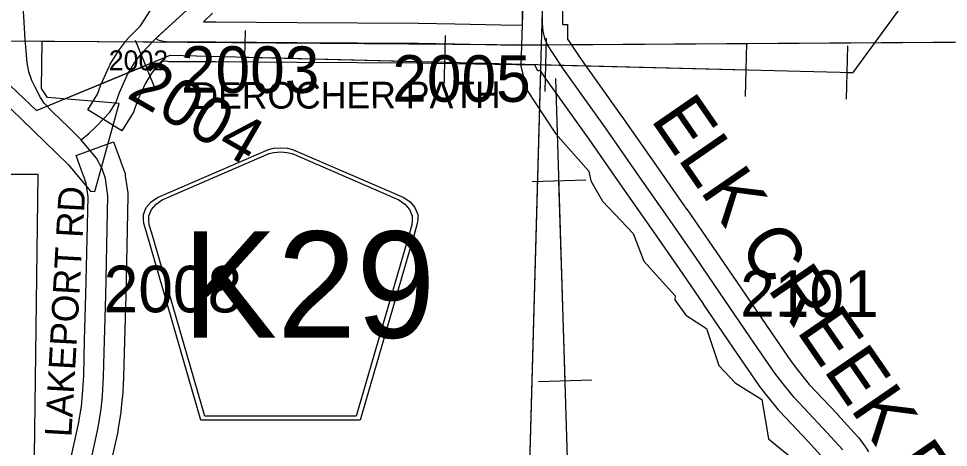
# Model space of a CAD drawing. Extents: x -157.2 to -99.3, y 12.2 to 46.2.
# Drawn here: x -145.492 to -144.094, y 31.449 to 32.094 of the extents above; entities that cross this region are included whole.
import ezdxf

# ---------------------------------------------------------------- set-up
doc = ezdxf.new("R2010")
doc.units = 0
for name, color, linetype in [('tdCoCityStreetMajor', 7, 'Continuous'), ('tdCoCorpBndry', 7, 'Continuous'), ('tdCoHydroRiver', 7, 'Continuous'), ('tdCoPipe', 7, 'Continuous'), ('tdCoSecRdNmbr', 7, 'Continuous'), ('tdCoSecRdTxt', 7, 'Continuous'), ('tdCoSecRteBand', 7, 'Continuous'), ('tdCoSecRteCL', 7, 'Continuous'), ('tdCoSectLine', 7, 'Continuous'), ('tdCoSectLinePart', 7, 'Continuous'), ('tdCoShieldCoRteHrd', 7, 'Continuous'), ('tdCoSurfAsphalt', 7, 'Continuous'), ('tdCoSurfConc', 7, 'Continuous'), ('tdCoSurfGravel', 7, 'Continuous')]:
    doc.layers.add(name, color=color, linetype=linetype)

msp = doc.modelspace()

# ---------------------------------------------------------------- linework, layer by layer
at = {"layer": 'tdCoCityStreetMajor'}
for points in [[(-145.4826, 32.0719), (-145.4857, 32.1228), (-145.4857, 32.1341)], [(-145.3976, 31.9117), (-145.4175, 31.9312), (-145.44, 31.9529), (-145.4535, 31.9672), (-145.4587, 31.9756), (-145.4671, 31.9911), (-145.4718, 32.001), (-145.4765, 32.014), (-145.4792, 32.0278), (-145.4825, 32.0693), (-145.4826, 32.0719)], [(-145.3976, 31.9117), (-145.3865, 31.9216), (-145.3744, 31.9327), (-145.3547, 31.9534), (-145.3463, 31.9669)], [(-145.367, 31.8703), (-145.3749, 31.8841), (-145.3906, 31.9033), (-145.3976, 31.9117)]]:
    msp.add_lwpolyline(points, dxfattribs=at)
at = {"layer": 'tdCoCorpBndry'}
for points in [[(-145.6967, 32.3046), (-145.704, 32.0622), (-145.522, 32.0609), (-145.5232, 31.977), (-145.521, 31.9748), (-145.4172, 31.8746), (-145.384, 31.8344), (-145.377, 31.8339), (-145.367, 31.8703), (-145.3408, 31.9665), (-145.3463, 31.9669), (-145.4484, 31.9757), (-145.4575, 31.9893), (-145.4564, 32.0604), (-145.2906, 32.0592), (-145.2854, 32.0644), (-145.2444, 32.1019)], [(-145.5039, 31.024), (-145.4868, 31.0282), (-145.4655, 31.0319), (-145.4654, 31.0504), (-145.4615, 31.0765), (-145.4394, 31.1714), (-145.4238, 31.2368), (-145.3841, 31.3971), (-145.3909, 31.3967), (-145.4684, 31.3974), (-145.4626, 31.8596), (-145.7085, 31.8599)]]:
    msp.add_lwpolyline(points, dxfattribs=at)
at = {"layer": 'tdCoHydroRiver'}
msp.add_lwpolyline([(-144.7325, 32.1474), (-144.7366, 32.0228), (-144.7283, 31.9878), (-144.6847, 31.9216), (-144.6344, 31.8647), (-144.6317, 31.8504), (-144.6138, 31.8198), (-144.568, 31.7709), (-144.552, 31.7293), (-144.5048, 31.6772), (-144.505, 31.6709), (-144.4884, 31.6482), (-144.4575, 31.6282), (-144.4388, 31.5723), (-144.4144, 31.5463), (-144.3742, 31.5212), (-144.3645, 31.4621), (-144.32, 31.4258), (-144.2447, 31.3274)], dxfattribs=at)
at = {"layer": 'tdCoPipe'}
for p, q in [((-145.1528, 31.9959), (-145.1508, 32.0763)), ((-145.2854, 31.9866), (-145.3162, 32.0611)), ((-144.8519, 31.9883), (-144.8499, 32.0689)), ((-144.6999, 31.9845), (-144.6979, 32.0649)), ((-144.399, 31.9769), (-144.397, 32.0574)), ((-144.247, 31.973), (-144.245, 32.0534)), ((-144.6392, 31.8513), (-144.7197, 31.8488)), ((-144.6298, 31.5504), (-144.7102, 31.5479))]:
    msp.add_line(p, q, dxfattribs=at)
for points in [[(-145.5545, 32.0407), (-145.4652, 31.9559), (-145.2641, 32.039), (-144.2371, 32.0131), (-143.232, 33.3859), (-142.9301, 33.9124), (-142.0867, 34.756), (-141.6374, 35.6825), (-141.5355, 35.8566), (-140.3685, 37.1582), (-139.4239, 38.0364), (-138.0693, 39.5013), (-138.0266, 39.825), (-137.4064, 40.3449), (-136.8596, 41.0707)], [(-144.246, 32.0133), (-144.2371, 32.0131), (-144.0645, 32.2488)], [(-145.5545, 32.0407), (-145.4652, 31.9559), (-145.3008, 32.0239)], [(-145.1518, 32.0362), (-144.8509, 32.0286)], [(-144.6989, 32.0248), (-144.398, 32.0171)], [(-147.1212, 25.0341), (-146.8959, 25.966), (-146.8533, 26.3456), (-146.8295, 27.003), (-146.6367, 27.3776), (-145.9154, 27.4375), (-145.9326, 27.6455), (-145.5021, 27.6971), (-145.5064, 28.1719), (-145.3821, 28.2336), (-145.5249, 28.9444), (-144.8928, 29.2745), (-144.8343, 30.559), (-144.6513, 30.9418), (-144.6842, 32.0039)], [(-144.6701, 31.5491), (-144.6794, 31.85)]]:
    msp.add_lwpolyline(points, dxfattribs=at)
at = {"layer": 'tdCoSecRteBand'}
for points in [[(-145.2004, 32.1023), (-145.2139, 32.0894), (-145.1954, 32.0894), (-145.1953, 32.0894), (-145.1951, 32.0894), (-145.0729, 32.0882), (-144.8912, 32.0872), (-144.891, 32.0872), (-144.8908, 32.0872), (-144.8358, 32.0862), (-144.8358, 32.0862), (-144.8358, 32.0862), (-144.7437, 32.0845), (-144.7342, 32.0846), (-144.7343, 32.0857), (-144.7343, 32.0875), (-144.7336, 32.1296)], [(-144.6736, 32.1283), (-144.6743, 32.0882), (-144.674, 32.0851), (-144.6666, 32.0851), (-144.6664, 32.0633), (-144.6642, 32.0597), (-144.6478, 32.0355), (-144.5852, 31.9472), (-144.5851, 31.9471), (-144.585, 31.9471), (-144.5335, 31.8733), (-144.4874, 31.8075), (-144.4873, 31.8074), (-144.4873, 31.8073), (-144.4488, 31.7516), (-144.4488, 31.7515), (-144.4487, 31.7515), (-144.4127, 31.6987), (-144.361, 31.623), (-144.3302, 31.5784), (-144.3208, 31.5657), (-144.3034, 31.5439), (-144.2608, 31.4989), (-144.2606, 31.4987), (-144.2604, 31.4985), (-144.2306, 31.4657), (-144.2296, 31.4646), (-144.2287, 31.4634), (-144.2195, 31.451), (-144.219, 31.4503), (-144.2184, 31.4494), (-144.214, 31.4425)], [(-144.276, 31.4265), (-144.3046, 31.4579), (-144.3478, 31.5036), (-144.3487, 31.5045), (-144.3495, 31.5055), (-144.368, 31.5287), (-144.3683, 31.5291), (-144.3686, 31.5294), (-144.3787, 31.543), (-144.379, 31.5435), (-144.3793, 31.5439), (-144.4104, 31.5891), (-144.4104, 31.5891), (-144.4105, 31.5891), (-144.4623, 31.6648), (-144.4623, 31.6649), (-144.4623, 31.6649), (-144.4982, 31.7176), (-144.5366, 31.7732), (-144.5827, 31.8389), (-144.5827, 31.8389), (-144.5827, 31.8389), (-144.6341, 31.9126), (-144.697, 32.001), (-144.6972, 32.0013), (-144.6974, 32.0016), (-144.7075, 32.0167), (-144.711, 32.0151), (-144.7155, 32.0247), (-144.7436, 32.0245), (-144.744, 32.0245), (-144.7444, 32.0245), (-144.8369, 32.0262), (-144.8917, 32.0272), (-145.0732, 32.0282), (-145.0733, 32.0282), (-145.0734, 32.0282), (-145.1956, 32.0294), (-145.2649, 32.0294), (-145.2662, 32.0294), (-145.2674, 32.0295), (-145.2765, 32.0303), (-145.2769, 32.0303), (-145.2843, 32.0224), (-145.2927, 32.0111), (-145.3016, 31.9962), (-145.3125, 31.9721), (-145.3175, 31.9578), (-145.3186, 31.9547), (-145.3203, 31.9519), (-145.3207, 31.9512), (-145.3365, 31.9256), (-145.3876, 31.9572), (-145.373, 31.9807), (-145.3687, 31.9931), (-145.3683, 31.9944), (-145.3677, 31.9955), (-145.3557, 32.0224), (-145.3549, 32.024), (-145.354, 32.0255), (-145.3434, 32.0433), (-145.3426, 32.0446), (-145.3417, 32.0459), (-145.3313, 32.0597), (-145.3304, 32.061), (-145.3292, 32.0622), (-145.3275, 32.064), (-145.3278, 32.0644), (-145.3088, 32.0834), (-145.2941, 32.1059)], [(-145.4148, 31.4252), (-145.4017, 31.4848), (-145.3975, 31.5109), (-145.3957, 31.5289), (-145.394, 31.5569), (-145.3926, 31.6109), (-145.3926, 31.611), (-145.3926, 31.611), (-145.3906, 31.6787), (-145.3875, 31.8261), (-145.3904, 31.8465), (-145.395, 31.8593), (-145.3952, 31.8601), (-145.4054, 31.8883), (-145.349, 31.9087), (-145.3388, 31.8804), (-145.3385, 31.8796), (-145.3385, 31.8796), (-145.3385, 31.8796), (-145.3328, 31.8639), (-145.3318, 31.861), (-145.3314, 31.8579), (-145.3278, 31.832), (-145.3274, 31.8296), (-145.3275, 31.8272), (-145.3306, 31.6773), (-145.3306, 31.6772), (-145.3306, 31.6771), (-145.3326, 31.6093), (-145.3341, 31.5548), (-145.3341, 31.5543), (-145.3341, 31.5538), (-145.3358, 31.5247), (-145.3359, 31.5241), (-145.3359, 31.5235), (-145.3379, 31.504), (-145.338, 31.5032), (-145.3381, 31.5023), (-145.3426, 31.4745), (-145.3427, 31.4736), (-145.3429, 31.4727), (-145.3555, 31.4155)]]:
    msp.add_lwpolyline(points, dxfattribs=at)
at = {"layer": 'tdCoSecRteCL'}
for points in [[(-145.2854, 32.0644), (-145.2832, 32.0666), (-145.2444, 32.1019), (-145.221, 32.1241), (-145.2104, 32.1356), (-145.2099, 32.1363), (-145.2038, 32.1445), (-145.1996, 32.1527), (-145.1941, 32.1642), (-145.189, 32.182), (-145.1875, 32.1946), (-145.1872, 32.2219), (-145.187, 32.2478), (-145.1865, 32.257)], [(-144.6964, 32.0549), (-144.7001, 32.063), (-144.7031, 32.0751), (-144.7043, 32.087), (-144.7036, 32.1291)], [(-145.3463, 31.9669), (-145.3458, 31.9677), (-145.3404, 31.9832), (-145.3283, 32.0101), (-145.3177, 32.0279), (-145.3073, 32.0417), (-145.2967, 32.053), (-145.2906, 32.0592), (-145.2906, 32.0592), (-145.2854, 32.0644)], [(-145.2854, 32.0644), (-145.2812, 32.0616), (-145.2741, 32.0602), (-145.2649, 32.0594), (-145.1954, 32.0594), (-145.0731, 32.0582), (-144.8913, 32.0572), (-144.8363, 32.0562), (-144.7439, 32.0545), (-144.6964, 32.0549)], [(-144.2528, 31.4455), (-144.2826, 31.4783), (-144.326, 31.5242), (-144.3445, 31.5474), (-144.3546, 31.5609), (-144.3857, 31.6061), (-144.4375, 31.6818), (-144.4735, 31.7346), (-144.512, 31.7903), (-144.5581, 31.8561), (-144.6096, 31.9299), (-144.6725, 32.0184), (-144.6893, 32.0433), (-144.6957, 32.0534), (-144.6964, 32.0549)], [(-145.3909, 31.3967), (-145.3855, 31.4185), (-145.3855, 31.4188), (-145.3722, 31.4792), (-145.3677, 31.507), (-145.3658, 31.5265), (-145.364, 31.5556), (-145.3626, 31.6101), (-145.3606, 31.6779), (-145.3575, 31.8278), (-145.3611, 31.8537), (-145.3667, 31.8695), (-145.367, 31.8703)]]:
    msp.add_lwpolyline(points, dxfattribs=at)
at = {"layer": 'tdCoSectLine'}
for points in [[(-144.7058, 32.0548), (-144.6749, 33.0564)], [(-145.7044, 32.0622), (-144.7058, 32.0548)], [(-144.7058, 32.0548), (-143.698, 32.0615)], [(-144.7336, 31.0461), (-144.7058, 32.0548)]]:
    msp.add_lwpolyline(points, dxfattribs=at)
at = {"layer": 'tdCoSectLinePart'}
for points in [[(-144.6611, 32.0551), (-143.728, 32.0613)], [(-144.7316, 31.1172), (-144.7069, 32.0156)]]:
    msp.add_lwpolyline(points, dxfattribs=at)
at = {"layer": 'tdCoShieldCoRteHrd'}
for points in [[(-145.2177, 31.4899), (-145.2997, 31.7728), (-145.3035, 31.7859), (-145.3043, 31.7918), (-145.3043, 31.7996), (-145.3, 31.8099), (-145.2927, 31.8184), (-145.2832, 31.8251), (-145.1159, 31.8974), (-145.1084, 31.8991), (-145.098, 31.9), (-145.0875, 31.8991), (-145.08, 31.8974), (-144.9127, 31.8251), (-144.9032, 31.8184), (-144.8959, 31.8099), (-144.8916, 31.7996), (-144.8916, 31.7918), (-144.8924, 31.7859), (-144.8963, 31.7728), (-144.9782, 31.4899)], [(-145.2119, 31.4962), (-145.2916, 31.7715), (-145.2953, 31.7841), (-145.296, 31.7898), (-145.296, 31.7973), (-145.2919, 31.8072), (-145.285, 31.8153), (-145.2758, 31.8217), (-145.1152, 31.8912), (-145.108, 31.8927), (-145.098, 31.8936), (-145.0879, 31.8927), (-145.0807, 31.8912), (-144.9201, 31.8217), (-144.911, 31.8153), (-144.904, 31.8072), (-144.8999, 31.7973), (-144.8999, 31.7898), (-144.9006, 31.7841), (-144.9043, 31.7715), (-144.9841, 31.4962)]]:
    msp.add_lwpolyline(points, close=True, dxfattribs=at)
at = {"layer": 'tdCoSurfAsphalt'}
for points in [[(-145.2854, 32.0644), (-145.2812, 32.0616), (-145.2741, 32.0602), (-145.2649, 32.0594), (-145.1954, 32.0594), (-145.0731, 32.0582)], [(-145.0731, 32.0582), (-144.8913, 32.0572), (-144.8363, 32.0562), (-144.7439, 32.0545), (-144.6964, 32.0549)]]:
    msp.add_lwpolyline(points, dxfattribs=at)
at = {"layer": 'tdCoSurfConc'}
msp.add_line((-145.2906, 32.0592), (-145.2906, 32.0592), dxfattribs=at)
for points in [[(-145.2906, 32.0592), (-145.2854, 32.0644), (-145.2832, 32.0666), (-145.2444, 32.1019), (-145.221, 32.1241), (-145.2104, 32.1356), (-145.2099, 32.1363), (-145.2038, 32.1445), (-145.1996, 32.1527), (-145.1941, 32.1642), (-145.189, 32.182), (-145.1875, 32.1946), (-145.1872, 32.2219), (-145.187, 32.2478), (-145.1865, 32.257)], [(-145.3463, 31.9669), (-145.3458, 31.9677), (-145.3404, 31.9832), (-145.3283, 32.0101), (-145.3177, 32.0279), (-145.3073, 32.0417), (-145.2967, 32.053), (-145.2906, 32.0592)], [(-145.3909, 31.3967), (-145.3855, 31.4185), (-145.3855, 31.4188), (-145.3722, 31.4792), (-145.3677, 31.507), (-145.3658, 31.5265), (-145.364, 31.5556), (-145.3626, 31.6101), (-145.3606, 31.6779), (-145.3575, 31.8278), (-145.3611, 31.8537), (-145.3667, 31.8695), (-145.367, 31.8703)]]:
    msp.add_lwpolyline(points, dxfattribs=at)
at = {"layer": 'tdCoSurfGravel'}
for points in [[(-144.6964, 32.0549), (-144.7001, 32.063), (-144.7031, 32.0751), (-144.7043, 32.087), (-144.7036, 32.1291), (-144.7014, 32.1927), (-144.6981, 32.3033)], [(-144.2528, 31.4455), (-144.2826, 31.4783), (-144.326, 31.5242), (-144.3445, 31.5474), (-144.3546, 31.5609), (-144.3857, 31.6061), (-144.4375, 31.6818), (-144.4735, 31.7346), (-144.512, 31.7903), (-144.5581, 31.8561), (-144.6096, 31.9299), (-144.6725, 32.0184), (-144.6893, 32.0433), (-144.6957, 32.0534), (-144.6964, 32.0549)]]:
    msp.add_lwpolyline(points, dxfattribs=at)

# ---------------------------------------------------------------- texts
at = {"layer": 'tdCoSecRdNmbr'}
for s, height, rotation, p in [('2002', 0.03, 359.8894, (-145.3563, 32.0165)), ('2003', 0.07, 359.8892, (-145.248, 31.9827)), ('2004', 0.07, 329.8891, (-145.3312, 31.9765)), ('2005', 0.07, 359.8894, (-144.9301, 31.9693)), ('2008', 0.07, 359.8891, (-145.364, 31.6526)), ('2101', 0.07, 359.8898, (-144.407, 31.6457))]:
    msp.add_text(s, height=height, rotation=rotation, dxfattribs=at).set_placement(p)
at = {"layer": 'tdCoSecRdTxt'}
for s, height, rotation, p in [('DEROCHER PATH', 0.04, 0.1572, (-145.2306, 31.9584)), ('ELK CREEK RD', 0.08, 304.5813, (-144.5427, 31.9426)), ('LAKEPORT RD', 0.04, 86.7655, (-145.4126, 31.4641))]:
    msp.add_text(s, height=height, rotation=rotation, dxfattribs=at).set_placement(p)
at = {"layer": 'tdCoShieldCoRteHrd'}
msp.add_text('K29', height=0.16, dxfattribs=at).set_placement((-145.2459, 31.6141))

doc.saveas('drawing.dxf')
